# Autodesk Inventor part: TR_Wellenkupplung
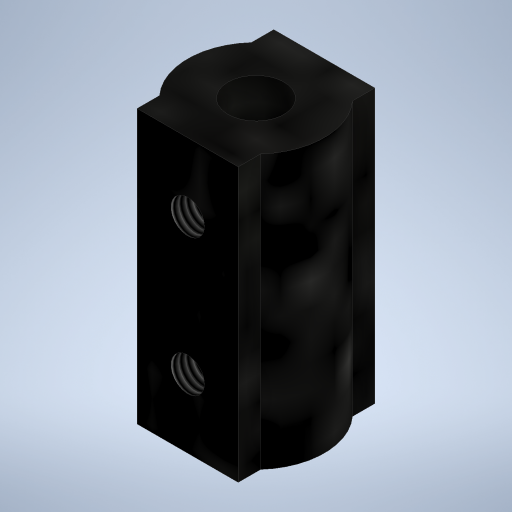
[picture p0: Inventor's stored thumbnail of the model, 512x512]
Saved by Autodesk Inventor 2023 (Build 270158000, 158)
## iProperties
Created: 2023-11
Part Number: TR_Wellenkupplung
Material: PC/ABS-Kunststoff
Document SubType Name: Modeling
Designer: Administrator
Density: 0.357273 g/cm^3
Appearance: Glatt - Schwarz
Author: Administrator
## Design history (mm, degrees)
sketch "Skizze1"
  geometry: C1 r 5 at (0, 0); 1 further point
  constraints: 1 centre point, 1 coincident
  dimensions: "d0" = 10 diameter of C1 (= Einheitsmaß)
extrude "Extrusion1" new body sketch "Skizze1" distance "d1" = 20; taper "d2" = 0 deg
sketch "Skizze2"
  geometry: L1 (-3.7, 20)-(3.7, 20); L2 (3.7, 20)-(3.7, 0); L3 (3.7, 0)-(-3.7, 0); L4 (-3.7, 0)-(-3.7, 20); L5 (-5, 0)-(-5, 20) reference; 4 further points
  constraints: 8 end point, 3 midpoint, 2 horizontal alignment, 2 parallel, 1 horizontal, 1 perpendicular, 1 vertical alignment
  dimensions: "d3" = 7.4 distance of L2.end L3.end
extrude "Extrusion2" join sketch "Skizze2" stored distance "d5" = 10; taper "d6" = 0 deg
sketch "Skizze5"
  geometry: C1 r 2.05 at (0, 0); 1 further point
  constraints: 1 centre point, 1 coincident
  dimensions: "d17" = 4.1 diameter of C1 (= DAchsAufnahme)
extrude "Extrusion4" cut sketch "Skizze5" extent not by distance; stored distance "d18" = 0; taper "d19" = 0 deg
sketch "Skizze6"
  geometry: L1 (0, 15)-(0, 5); L2 (-3.7, 20)-(-3.7, 0) reference; L3 (-3.7, 0)-(3.7, 0) reference; 4 further points
  constraints: 3 midpoint, 2 end point, 1 horizontal alignment, 1 vertical, 1 vertical alignment
  dimensions: "d20" = 10 distance of L1.end L1.start
hole "Bohrung2" sketch "Skizze6" at (0, 5), (0, 15) diameter "d21" = 2.459; stored, may be unused: countersink angle "d25" = 90 deg, drill point angle "d27" = 118 deg; dims "d22" = 10, "d23" = 4, "d24" = 2, "d26" = 8
node "Volumenkörper1"
other parameters: "Einheitsmaß" = 10 [user parameter; used in 1 equation term], "Radius" = 2.075 [user parameter], "Fasen" = 0.5 [user parameter], "Dicke" = 0.8 [user parameter], "Breitloch" = 2 [user parameter], "Langloch" = 32 [user parameter], "AchteckUmkreis" = 6 [user parameter], "DAchsAufnahme" = 4.1 [user parameter; used in 1 equation term], "AchsDurchmesser" = 4 [user parameter], "AchsFase" = 0.5 [user parameter]
